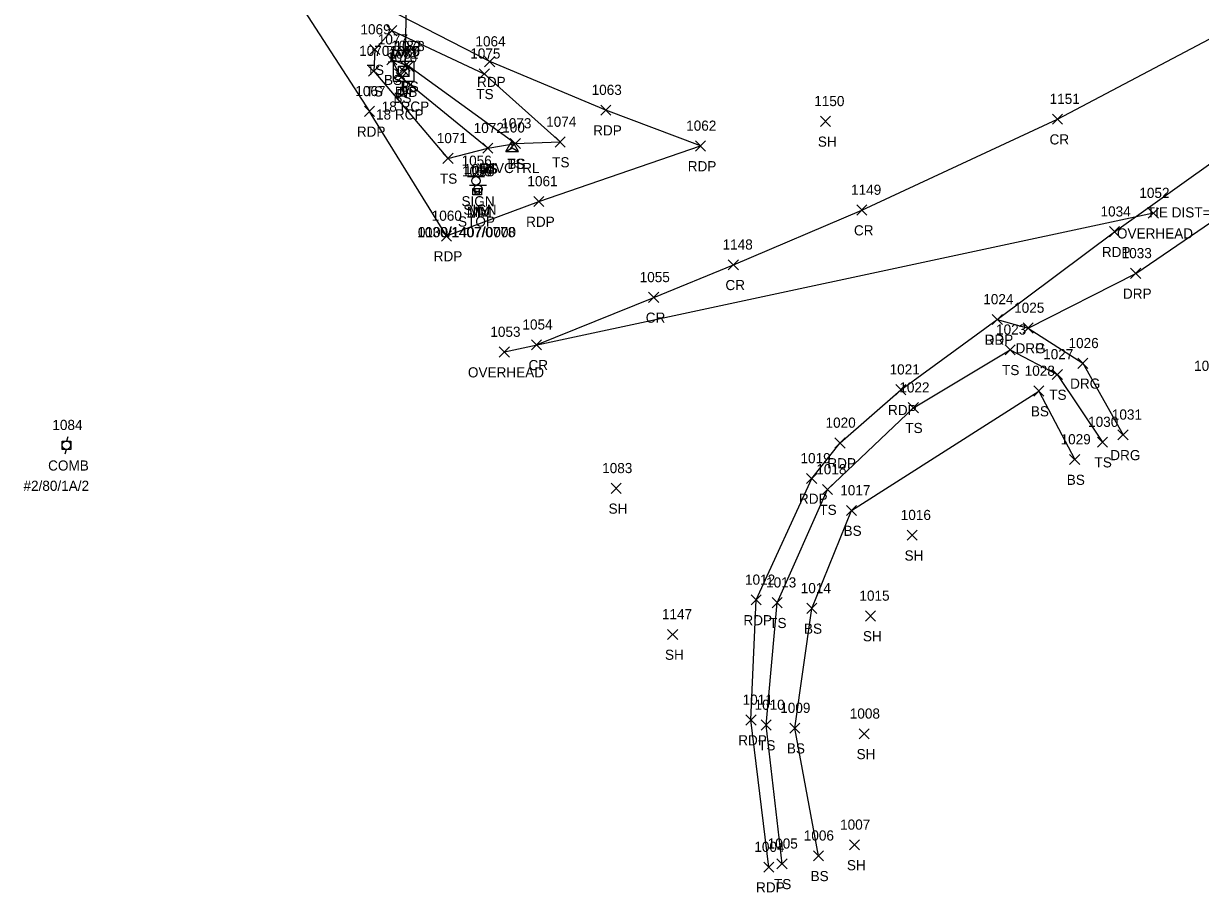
# Model space of a CAD drawing. Extents: x 1611797 to 1633212, y 298978 to 305475.
# Drawn here: x 1611998 to 1612230.1, y 300322.7 to 300494.1 of the extents above; entities that cross this region are included whole.
import ezdxf

# ---------------------------------------------------------------- set-up
doc = ezdxf.new("R2010")
doc.units = 0
for name, color, linetype in [('C_A', 7, 'Continuous'), ('C_C', 7, 'Continuous'), ('C_I', 7, 'Continuous'), ('CPSM', 7, 'Continuous'), ('D_A', 7, 'Continuous'), ('D_C', 7, 'Continuous'), ('D_I', 7, 'Continuous'), ('D_TIC', 7, 'Continuous'), ('DCP', 7, 'Continuous'), ('DS', 7, 'Continuous'), ('L_A', 7, 'Continuous'), ('L_I', 7, 'Continuous'), ('L_TIC', 7, 'Continuous'), ('LELB', 7, 'Continuous'), ('P_A', 7, 'Continuous'), ('P_I', 7, 'Continuous'), ('P_TIC', 7, 'Continuous'), ('PET', 7, 'Continuous'), ('PRC', 7, 'Continuous'), ('R_A', 7, 'Continuous'), ('R_I', 7, 'Continuous'), ('R_TIC', 7, 'Continuous'), ('RDG', 7, 'Continuous'), ('RDP', 7, 'Continuous'), ('S_A', 7, 'Continuous'), ('S_C', 7, 'Continuous'), ('S_I', 7, 'Continuous'), ('SRM', 7, 'Continuous'), ('SSGN', 7, 'Continuous'), ('U_A', 7, 'Continuous'), ('U_C', 7, 'Continuous'), ('U_I', 7, 'Continuous'), ('U_TIC', 7, 'Continuous'), ('UCO', 7, 'Continuous'), ('UP', 7, 'Continuous')]:
    doc.layers.add(name, color=color, linetype=linetype)

msp = doc.modelspace()

# ---------------------------------------------------------------- linework, layer by layer
at = {"layer": 'CPSM'}
for p, q in [((1612093.1, 300468.85), (1612094.35, 300471.02)), ((1612095.6, 300468.85), (1612094.35, 300471.02)), ((1612094.35, 300469.57), (1612094.35, 300471.02)), ((1612093.1, 300468.85), (1612094.35, 300469.57)), ((1612093.1, 300468.85), (1612095.6, 300468.85)), ((1612094.35, 300469.57), (1612094.35, 300469.57)), ((1612094.35, 300469.57), (1612095.6, 300468.85))]:
    msp.add_line(p, q, dxfattribs=at)
at = {"layer": 'D_TIC'}
for points in [[(1612072.27, 300484.68), (1612074.27, 300486.68)], [(1612074.27, 300484.68), (1612072.27, 300486.68)], [(1612071.14, 300483.13), (1612073.14, 300485.13)], [(1612073.14, 300483.13), (1612071.14, 300485.13)], [(1612072.1, 300483.58), (1612074.1, 300485.58)], [(1612074.1, 300483.58), (1612072.1, 300485.58)]]:
    msp.add_lwpolyline(points, dxfattribs=at)
at = {"layer": 'DCP'}
msp.add_lwpolyline([(1612073.27, 300485.68), (1612074.52, 300542.7)], dxfattribs=at)
at = {"layer": 'DS'}
for p, q in [((1612070.95, 300486.63), (1612074.95, 300486.63)), ((1612070.95, 300482.63), (1612070.95, 300486.63)), ((1612074.95, 300486.63), (1612074.95, 300482.63)), ((1612071.95, 300483.63), (1612071.95, 300485.63)), ((1612071.95, 300485.63), (1612073.95, 300485.63)), ((1612072.96, 300484.63), (1612072.96, 300484.63)), ((1612072.96, 300484.63), (1612072.96, 300484.63)), ((1612073.95, 300485.63), (1612073.95, 300483.63)), ((1612074.95, 300482.63), (1612070.95, 300482.63)), ((1612073.95, 300483.63), (1612071.95, 300483.63))]:
    msp.add_line(p, q, dxfattribs=at)
at = {"layer": 'L_TIC'}
for points in [[(1612069.61, 300491.65), (1612071.61, 300493.65)], [(1612071.61, 300491.65), (1612069.61, 300493.65)], [(1612069.61, 300491.65), (1612071.61, 300493.65)], [(1612071.61, 300491.65), (1612069.61, 300493.65)], [(1612066.26, 300487.92), (1612068.26, 300489.92)], [(1612068.26, 300487.92), (1612066.26, 300489.92)], [(1612069.63, 300485.94), (1612071.63, 300487.94)], [(1612071.63, 300485.94), (1612069.63, 300487.94)], [(1612072.93, 300484.62), (1612074.93, 300486.62)], [(1612074.93, 300484.62), (1612072.93, 300486.62)], [(1612072.93, 300484.62), (1612074.93, 300486.62)], [(1612074.93, 300484.62), (1612072.93, 300486.62)], [(1612066.05, 300483.67), (1612068.05, 300485.67)], [(1612068.05, 300483.67), (1612066.05, 300485.67)], [(1612071.5, 300482.4), (1612073.5, 300484.4)], [(1612073.5, 300482.4), (1612071.5, 300484.4)], [(1612087.86, 300483.15), (1612089.86, 300485.15)], [(1612089.86, 300483.15), (1612087.86, 300485.15)], [(1612087.86, 300483.15), (1612089.86, 300485.15)], [(1612089.86, 300483.15), (1612087.86, 300485.15)], [(1612155.13, 300473.77), (1612157.13, 300475.77)], [(1612157.13, 300473.77), (1612155.13, 300475.77)], [(1612088.55, 300468.47), (1612090.55, 300470.47)], [(1612090.55, 300468.47), (1612088.55, 300470.47)], [(1612088.55, 300468.47), (1612090.55, 300470.47)], [(1612090.55, 300468.47), (1612088.55, 300470.47)], [(1612093.97, 300469.39), (1612095.97, 300471.39)], [(1612095.97, 300469.39), (1612093.97, 300471.39)], [(1612093.97, 300469.39), (1612095.97, 300471.39)], [(1612095.97, 300469.39), (1612093.97, 300471.39)], [(1612102.83, 300469.7), (1612104.83, 300471.7)], [(1612104.83, 300469.7), (1612102.83, 300471.7)], [(1612080.7, 300466.47), (1612082.7, 300468.47)], [(1612082.7, 300466.47), (1612080.7, 300468.47)], [(1612191.53, 300428.73), (1612193.53, 300430.73)], [(1612193.53, 300428.73), (1612191.53, 300430.73)], [(1612200.83, 300423.86), (1612202.83, 300425.86)], [(1612202.83, 300423.86), (1612200.83, 300425.86)], [(1612197.18, 300420.6), (1612199.18, 300422.6)], [(1612199.18, 300420.6), (1612197.18, 300422.6)], [(1612172.46, 300417.31), (1612174.46, 300419.31)], [(1612174.46, 300417.31), (1612172.46, 300419.31)], [(1612209.76, 300410.53), (1612211.76, 300412.53)], [(1612211.76, 300410.53), (1612209.76, 300412.53)], [(1612204.26, 300407.09), (1612206.26, 300409.09)], [(1612206.26, 300407.09), (1612204.26, 300409.09)], [(1612113.87, 300401.41), (1612115.87, 300403.41)], [(1612115.87, 300401.41), (1612113.87, 300403.41)], [(1612155.51, 300401.18), (1612157.51, 300403.18)], [(1612157.51, 300401.18), (1612155.51, 300403.18)], [(1612160.25, 300397.04), (1612162.25, 300399.04)], [(1612162.25, 300397.04), (1612160.25, 300399.04)], [(1612172.23, 300392.16), (1612174.23, 300394.16)], [(1612174.23, 300392.16), (1612172.23, 300394.16)], [(1612145.62, 300378.86), (1612147.62, 300380.86)], [(1612147.62, 300378.86), (1612145.62, 300380.86)], [(1612152.45, 300377.74), (1612154.45, 300379.74)], [(1612154.45, 300377.74), (1612152.45, 300379.74)], [(1612164.02, 300376.25), (1612166.02, 300378.25)], [(1612166.02, 300376.25), (1612164.02, 300378.25)], [(1612125, 300372.6), (1612127, 300374.6)], [(1612127, 300372.6), (1612125, 300374.6)], [(1612143.43, 300354.74), (1612145.43, 300356.74)], [(1612145.43, 300354.74), (1612143.43, 300356.74)], [(1612149.07, 300354.13), (1612151.07, 300356.13)], [(1612151.07, 300354.13), (1612149.07, 300356.13)], [(1612162.77, 300353.01), (1612164.77, 300355.01)], [(1612164.77, 300353.01), (1612162.77, 300355.01)], [(1612153.75, 300328.96), (1612155.75, 300330.96)], [(1612155.75, 300328.96), (1612153.75, 300330.96)], [(1612160.86, 300331.11), (1612162.86, 300333.11)], [(1612162.86, 300331.11), (1612160.86, 300333.11)], [(1612146.57, 300327.38), (1612148.57, 300329.38)], [(1612148.57, 300327.38), (1612146.57, 300329.38)]]:
    msp.add_lwpolyline(points, dxfattribs=at)
at = {"layer": 'LELB'}
for points in [[(1612070.61, 300492.65), (1612067.26, 300488.92), (1612067.05, 300484.67), (1612081.7, 300467.47), (1612089.55, 300469.47), (1612094.97, 300470.39), (1612103.83, 300470.7), (1612088.86, 300484.15)], [(1612070.61, 300492.65), (1612088.86, 300484.15)], [(1612089.55, 300469.47), (1612072.5, 300483.4), (1612070.63, 300486.94), (1612073.93, 300485.62)], [(1612094.97, 300470.39), (1612073.93, 300485.62)], [(1612147.57, 300328.38), (1612144.43, 300355.74), (1612146.62, 300379.86), (1612156.51, 300402.18), (1612173.46, 300418.31), (1612192.53, 300429.73), (1612201.83, 300424.86), (1612210.76, 300411.53)], [(1612154.75, 300329.96), (1612150.07, 300355.13), (1612153.45, 300378.74), (1612161.25, 300398.04), (1612198.18, 300421.6), (1612205.26, 300408.09)]]:
    msp.add_lwpolyline(points, dxfattribs=at)
at = {"layer": 'P_TIC'}
for points in [[(1612088.93, 300485.55), (1612090.93, 300487.55)], [(1612090.93, 300485.55), (1612088.93, 300487.55)], [(1612065.24, 300475.74), (1612067.24, 300477.74)], [(1612067.24, 300475.74), (1612065.24, 300477.74)], [(1612065.24, 300475.74), (1612067.24, 300477.74)], [(1612067.24, 300475.74), (1612065.24, 300477.74)], [(1612111.83, 300475.98), (1612113.83, 300477.98)], [(1612113.83, 300475.98), (1612111.83, 300477.98)], [(1612200.88, 300474.21), (1612202.88, 300476.21)], [(1612202.88, 300474.21), (1612200.88, 300476.21)], [(1612130.48, 300468.92), (1612132.48, 300470.92)], [(1612132.48, 300468.92), (1612130.48, 300470.92)], [(1612098.61, 300457.97), (1612100.61, 300459.97)], [(1612100.61, 300457.97), (1612098.61, 300459.97)], [(1612162.3, 300456.28), (1612164.3, 300458.28)], [(1612164.3, 300456.28), (1612162.3, 300458.28)], [(1612212.13, 300452.01), (1612214.13, 300454.01)], [(1612214.13, 300452.01), (1612212.13, 300454.01)], [(1612080.39, 300451.17), (1612082.39, 300453.17)], [(1612082.39, 300451.17), (1612080.39, 300453.17)], [(1612080.39, 300451.17), (1612082.39, 300453.17)], [(1612082.39, 300451.17), (1612080.39, 300453.17)], [(1612136.97, 300445.49), (1612138.97, 300447.49)], [(1612138.97, 300445.49), (1612136.97, 300447.49)], [(1612121.26, 300439.06), (1612123.26, 300441.06)], [(1612123.26, 300439.06), (1612121.26, 300441.06)], [(1612189.01, 300434.71), (1612191.01, 300436.71)], [(1612191.01, 300434.71), (1612189.01, 300436.71)], [(1612098.15, 300429.71), (1612100.15, 300431.71)], [(1612100.15, 300429.71), (1612098.15, 300431.71)], [(1612169.98, 300420.86), (1612171.98, 300422.86)], [(1612171.98, 300420.86), (1612169.98, 300422.86)], [(1612158, 300410.36), (1612160, 300412.36)], [(1612160, 300410.36), (1612158, 300412.36)], [(1612152.41, 300403.36), (1612154.41, 300405.36)], [(1612154.41, 300403.36), (1612152.41, 300405.36)], [(1612141.46, 300379.41), (1612143.46, 300381.41)], [(1612143.46, 300379.41), (1612141.46, 300381.41)], [(1612140.43, 300355.74), (1612142.43, 300357.74)], [(1612142.43, 300355.74), (1612140.43, 300357.74)], [(1612143.95, 300326.73), (1612145.95, 300328.73)], [(1612145.95, 300326.73), (1612143.95, 300328.73)]]:
    msp.add_lwpolyline(points, dxfattribs=at)
at = {"layer": 'PET'}
for points in [[(1612144.95, 300327.73), (1612141.43, 300356.74), (1612142.46, 300380.41), (1612153.41, 300404.36), (1612159, 300411.36), (1612170.98, 300421.86), (1612190.01, 300435.71), (1612213.13, 300453.01), (1612239.2, 300471.61), (1612262.51, 300487.14), (1612292.31, 300507.99), (1612320.91, 300529.26), (1612358.61, 300558.48), (1612393.41, 300587.37), (1612420.13, 300609.37), (1612455.86, 300639.27), (1612483.55, 300663.26), (1612507.62, 300684.04), (1612523.65, 300697.34), (1612526.47, 300698.16), (1612545.1, 300714.88), (1612575.4, 300740.47), (1612596.8, 300759.03)], [(1612081.39, 300452.17), (1612099.61, 300458.97), (1612131.48, 300469.92), (1612112.83, 300476.98), (1612089.93, 300486.55), (1612064.58, 300499.66), (1612043.48, 300511.85), (1612066.24, 300476.74)], [(1612081.39, 300452.17), (1612066.24, 300476.74)]]:
    msp.add_lwpolyline(points, dxfattribs=at)
at = {"layer": 'PRC'}
msp.add_lwpolyline([(1612099.15, 300430.71), (1612122.26, 300440.06), (1612137.97, 300446.49), (1612163.3, 300457.28), (1612201.88, 300475.21), (1612233.05, 300491.64), (1612256.74, 300506.56), (1612286.27, 300526.59), (1612308.68, 300543.56), (1612346.26, 300573.25), (1612380.66, 300601.4), (1612412.05, 300627.28), (1612443.59, 300653.56), (1612468.75, 300674.64), (1612494.08, 300695.8), (1612523, 300719.99), (1612546.51, 300739.43), (1612573.49, 300762.64), (1612603.84, 300788.89)], dxfattribs=at)
at = {"layer": 'R_TIC'}
for points in [[(1612216.29, 300443.79), (1612218.29, 300445.79)], [(1612218.29, 300443.79), (1612216.29, 300445.79)], [(1612189.01, 300434.71), (1612191.01, 300436.71)], [(1612191.01, 300434.71), (1612189.01, 300436.71)], [(1612195.1, 300433.02), (1612197.1, 300435.02)], [(1612197.1, 300433.02), (1612195.1, 300435.02)], [(1612195.1, 300433.02), (1612197.1, 300435.02)], [(1612197.1, 300433.02), (1612195.1, 300435.02)], [(1612205.87, 300426.06), (1612207.87, 300428.06)], [(1612207.87, 300426.06), (1612205.87, 300428.06)], [(1612213.8, 300411.96), (1612215.8, 300413.96)], [(1612215.8, 300411.96), (1612213.8, 300413.96)]]:
    msp.add_lwpolyline(points, dxfattribs=at)
at = {"layer": 'RDG'}
msp.add_lwpolyline([(1612196.1, 300434.02), (1612206.87, 300427.06), (1612214.8, 300412.96)], dxfattribs=at)
at = {"layer": 'RDP'}
msp.add_lwpolyline([(1612190.01, 300435.71), (1612196.1, 300434.02), (1612217.29, 300444.79), (1612234.92, 300456.78), (1612234.62, 300465.84), (1612239.2, 300471.61)], dxfattribs=at)
at = {"layer": 'SRM'}
for points in [[(1612086.61, 300461.54), (1612087.86, 300461.54), (1612087.86, 300460.29), (1612086.61, 300460.29)], [(1612087.05, 300461.55), (1612088.3, 300461.55), (1612088.3, 300460.3), (1612087.05, 300460.3)]]:
    msp.add_lwpolyline(points, close=True, dxfattribs=at)
for centre in [(1612087.24, 300460.92), (1612087.67, 300460.93)]:
    msp.add_circle(centre, 0.0833, dxfattribs=at)
at = {"layer": 'SSGN'}
for p, q in [((1612085.58, 300463.87), (1612088.91, 300463.87)), ((1612085.95, 300462.21), (1612089.29, 300462.21)), ((1612087.22, 300463.03), (1612087.22, 300463.03)), ((1612087.6, 300461.38), (1612087.6, 300461.38))]:
    msp.add_line(p, q, dxfattribs=at)
for centre in [(1612087.22, 300463.03), (1612087.6, 300461.38)]:
    msp.add_circle(centre, 0.833, dxfattribs=at)
at = {"layer": 'U_TIC'}
for points in [[(1612219.78, 300455.67), (1612221.78, 300457.67)], [(1612221.78, 300455.67), (1612219.78, 300457.67)], [(1612091.82, 300428.28), (1612093.82, 300430.28)], [(1612093.82, 300428.28), (1612091.82, 300430.28)]]:
    msp.add_lwpolyline(points, dxfattribs=at)
at = {"layer": 'UCO'}
msp.add_lwpolyline([(1612220.78, 300456.67), (1612092.82, 300429.28)], dxfattribs=at)
at = {"layer": 'UP'}
for p, q in [((1612006.72, 300412.57), (1612006.47, 300411.74)), ((1612005.64, 300410.07), (1612005.64, 300411.74)), ((1612005.64, 300411.74), (1612007.31, 300411.74)), ((1612007.31, 300410.07), (1612005.64, 300410.07)), ((1612006.22, 300409.24), (1612006.47, 300410.07)), ((1612006.47, 300410.91), (1612006.47, 300410.91)), ((1612007.31, 300411.74), (1612007.31, 300410.07))]:
    msp.add_line(p, q, dxfattribs=at)
msp.add_circle((1612006.47, 300410.91), 0.833, dxfattribs=at)

# ---------------------------------------------------------------- texts
at = {"layer": 'C_A'}
msp.add_text('HVCTRL', height=2, dxfattribs=at).set_placement((1612089.04, 300464.57))
at = {"layer": 'C_C'}
msp.add_text('TIE DIST=32.58 NAIL IN MB POST', height=2, dxfattribs=at).set_placement((1612219.49, 300455.82))
at = {"layer": 'C_I'}
msp.add_text('100', height=2, dxfattribs=at).set_placement((1612092.39, 300472.57))
at = {"layer": 'D_A'}
for s, p in [('P', (1612072.64, 300480.68)), ('DIB', (1612071.2, 300479.58)), ('P', (1612071.52, 300479.13)), ('DI', (1612072.01, 300479.63))]:
    msp.add_text(s, height=2, dxfattribs=at).set_placement(p)
at = {"layer": 'D_C'}
for p in [(1612067.51, 300475.13), (1612068.63, 300476.68)]:
    msp.add_text('18 RCP', height=2, dxfattribs=at).set_placement(p)
at = {"layer": 'D_I'}
for s, p in [('1081', (1612069.94, 300487.13)), ('1079', (1612070.18, 300487.63)), ('1080', (1612070.24, 300487.58)), ('1082', (1612070.49, 300488.68))]:
    msp.add_text(s, height=2, dxfattribs=at).set_placement(p)
at = {"layer": 'L_A'}
for s, p in [('TS', (1612069.02, 300487.65)), ('TS', (1612069.02, 300487.65)), ('TS', (1612065.67, 300483.92)), ('BS', (1612069.07, 300481.94)), ('BS', (1612072.37, 300480.62)), ('BS', (1612072.37, 300480.62)), ('TS', (1612065.46, 300479.67)), ('BS', (1612070.94, 300478.4)), ('TS', (1612087.27, 300479.15)), ('TS', (1612087.27, 300479.15)), ('SH', (1612154.62, 300469.77)), ('TS', (1612087.96, 300464.47)), ('BS', (1612087.99, 300464.47)), ('TS', (1612093.38, 300465.39)), ('BS', (1612093.42, 300465.39)), ('TS', (1612102.24, 300465.7)), ('TS', (1612080.11, 300462.47)), ('TS', (1612190.94, 300424.73)), ('TS', (1612200.24, 300419.86)), ('BS', (1612196.62, 300416.6)), ('TS', (1612171.87, 300413.31)), ('TS', (1612209.17, 300406.53)), ('BS', (1612203.7, 300403.09)), ('SH', (1612113.36, 300397.41)), ('TS', (1612154.92, 300397.18)), ('BS', (1612159.69, 300393.04)), ('SH', (1612171.72, 300388.16)), ('TS', (1612145.03, 300374.86)), ('BS', (1612151.89, 300373.74)), ('SH', (1612163.51, 300372.25)), ('SH', (1612124.49, 300368.6)), ('TS', (1612142.84, 300350.74)), ('BS', (1612148.51, 300350.13)), ('SH', (1612162.26, 300349.01)), ('SH', (1612160.35, 300327.11)), ('BS', (1612153.19, 300324.96)), ('TS', (1612145.98, 300323.38))]:
    msp.add_text(s, height=2, dxfattribs=at).set_placement(p)
at = {"layer": 'L_I'}
for s, p in [('1069', (1612064.44, 300491.92)), ('1077', (1612067.86, 300489.94)), ('1070', (1612064.19, 300487.67)), ('1078', (1612071.16, 300488.62)), ('1078', (1612071.16, 300488.62)), ('1075', (1612086.09, 300487.15)), ('1075', (1612086.09, 300487.15)), ('1076', (1612069.67, 300486.4)), ('1150', (1612153.91, 300477.77)), ('1073', (1612092.2, 300473.39)), ('1073', (1612092.2, 300473.39)), ('1074', (1612101.06, 300473.7)), ('1071', (1612079.49, 300470.47)), ('1072', (1612086.77, 300472.47)), ('1072', (1612086.77, 300472.47)), ('1023', (1612189.76, 300432.73)), ('1027', (1612199.05, 300427.86)), ('1028', (1612195.41, 300424.6)), ('1032', (1612228.81, 300425.57)), ('1022', (1612170.69, 300421.31)), ('1030', (1612207.91, 300414.53)), ('1029', (1612202.48, 300411.09)), ('1083', (1612112.1, 300405.41)), ('1018', (1612154.31, 300405.18)), ('1017', (1612159.04, 300401.04)), ('1016', (1612170.97, 300396.16)), ('1013', (1612144.42, 300382.86)), ('1014', (1612151.25, 300381.74)), ('1015', (1612162.82, 300380.25)), ('1147', (1612123.88, 300376.6)), ('1010', (1612142.14, 300358.74)), ('1009', (1612147.21, 300358.13)), ('1008', (1612160.92, 300357.01)), ('1007', (1612159.01, 300335.11)), ('1005', (1612144.72, 300331.38)), ('1006', (1612151.85, 300332.96))]:
    msp.add_text(s, height=2, dxfattribs=at).set_placement(p)
at = {"layer": 'P_A'}
for s, p in [('RDP', (1612087.42, 300481.55)), ('RDP', (1612063.73, 300471.74)), ('RDP', (1612063.73, 300471.74)), ('RDP', (1612110.32, 300471.98)), ('CR', (1612200.31, 300470.21)), ('RDP', (1612128.97, 300464.92)), ('RDP', (1612097.1, 300453.97)), ('CR', (1612161.74, 300452.28)), ('RDP', (1612210.62, 300448.01)), ('RDP', (1612078.88, 300447.17)), ('RDP', (1612078.88, 300447.17)), ('CR', (1612136.4, 300441.49)), ('CR', (1612120.69, 300435.06)), ('RDP', (1612187.5, 300430.71)), ('CR', (1612097.58, 300425.71)), ('RDP', (1612168.46, 300416.86)), ('RDP', (1612156.49, 300406.36)), ('RDP', (1612150.9, 300399.36)), ('RDP', (1612139.95, 300375.41)), ('RDP', (1612138.92, 300351.74)), ('RDP', (1612142.44, 300322.73))]:
    msp.add_text(s, height=2, dxfattribs=at).set_placement(p)
at = {"layer": 'P_I'}
for s, p in [('1064', (1612087.11, 300489.55)), ('1067', (1612063.43, 300479.74)), ('1067', (1612063.43, 300479.74)), ('1063', (1612110.02, 300479.98)), ('1151', (1612200.32, 300478.21)), ('1062', (1612128.66, 300472.92)), ('1061', (1612097.36, 300461.97)), ('1149', (1612161.17, 300460.28)), ('1060', (1612078.49, 300455.17)), ('1060', (1612078.49, 300455.17)), ('1034', (1612210.36, 300456.01)), ('1148', (1612135.84, 300449.49)), ('1055', (1612119.49, 300443.06)), ('1024', (1612187.24, 300438.71)), ('1054', (1612096.38, 300433.71)), ('1021', (1612168.77, 300424.86)), ('1020', (1612156.14, 300414.36)), ('1019', (1612151.2, 300407.36)), ('1012', (1612140.26, 300383.41)), ('1011', (1612139.79, 300359.74)), ('1004', (1612142.1, 300330.73))]:
    msp.add_text(s, height=2, dxfattribs=at).set_placement(p)
at = {"layer": 'R_A'}
for s, p in [('DRP', (1612214.78, 300439.79)), ('DRP', (1612187.5, 300430.71)), ('DRG', (1612193.59, 300429.02)), ('DRP', (1612193.59, 300429.02)), ('DRG', (1612204.36, 300422.06)), ('DRG', (1612212.28, 300407.96))]:
    msp.add_text(s, height=2, dxfattribs=at).set_placement(p)
at = {"layer": 'R_I'}
for s, p in [('1033', (1612214.52, 300447.79)), ('1024', (1612187.24, 300438.71)), ('1025', (1612193.33, 300437.02)), ('1025', (1612193.33, 300437.02)), ('1026', (1612204.05, 300430.06)), ('1031', (1612212.59, 300415.96))]:
    msp.add_text(s, height=2, dxfattribs=at).set_placement(p)
at = {"layer": 'S_A'}
for s, p in [('SIGN', (1612084.36, 300458.01)), ('SIGN', (1612084.74, 300456.36)), ('MM', (1612085.43, 300455.92)), ('MM', (1612085.86, 300455.93))]:
    msp.add_text(s, height=2, dxfattribs=at).set_placement(p)
at = {"layer": 'S_C'}
for s, p in [('1030/1407/0778', (1612075.66, 300451.92)), ('0100/1407/0000', (1612075.77, 300451.93)), ('STOP', (1612083.68, 300454.01))]:
    msp.add_text(s, height=2, dxfattribs=at).set_placement(p)
at = {"layer": 'S_I'}
for s, p in [('1056', (1612084.38, 300466.01)), ('1059', (1612084.46, 300463.92)), ('1057', (1612084.81, 300464.36)), ('1058', (1612084.9, 300463.93))]:
    msp.add_text(s, height=2, dxfattribs=at).set_placement(p)
at = {"layer": 'U_A'}
for s, p in [('OVERHEAD', (1612213.59, 300451.67)), ('OVERHEAD', (1612085.63, 300424.28)), ('COMB', (1612002.86, 300405.91))]:
    msp.add_text(s, height=2, dxfattribs=at).set_placement(p)
at = {"layer": 'U_C'}
msp.add_text('#2/80/1A/2', height=2, dxfattribs=at).set_placement((1611998, 300401.91))
at = {"layer": 'U_I'}
for s, p in [('1052', (1612218.01, 300459.67)), ('1053', (1612090.05, 300432.28)), ('1084', (1612003.7, 300413.91))]:
    msp.add_text(s, height=2, dxfattribs=at).set_placement(p)

doc.saveas('drawing.dxf')
